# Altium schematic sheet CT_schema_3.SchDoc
size 451 x 443 mm
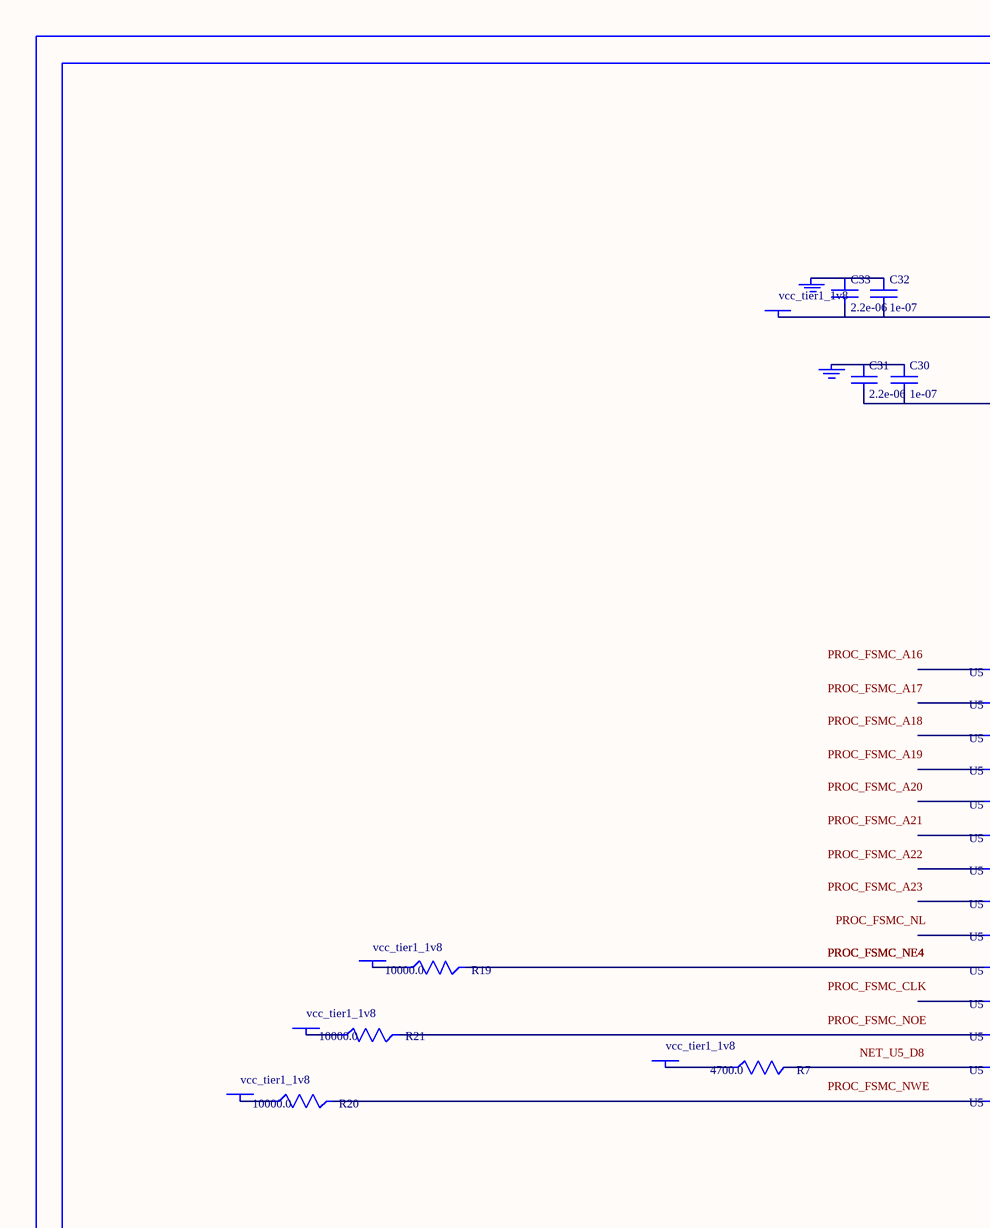
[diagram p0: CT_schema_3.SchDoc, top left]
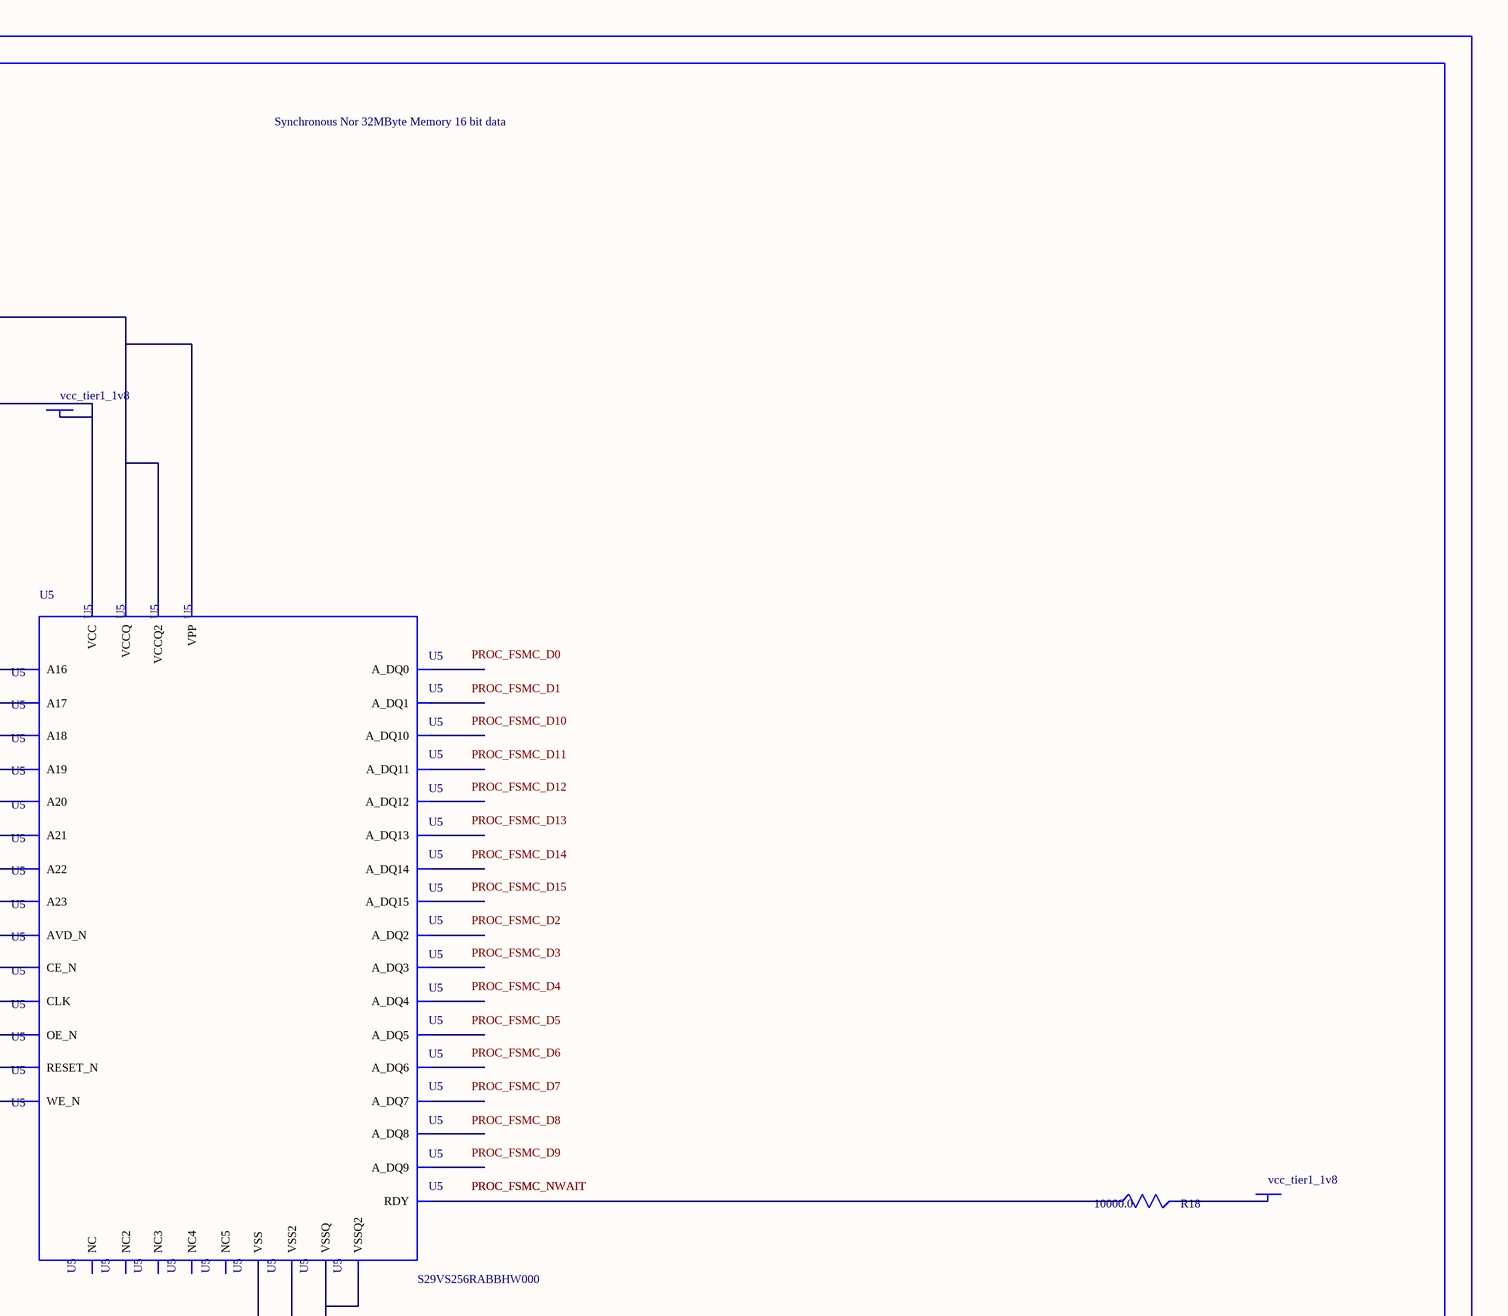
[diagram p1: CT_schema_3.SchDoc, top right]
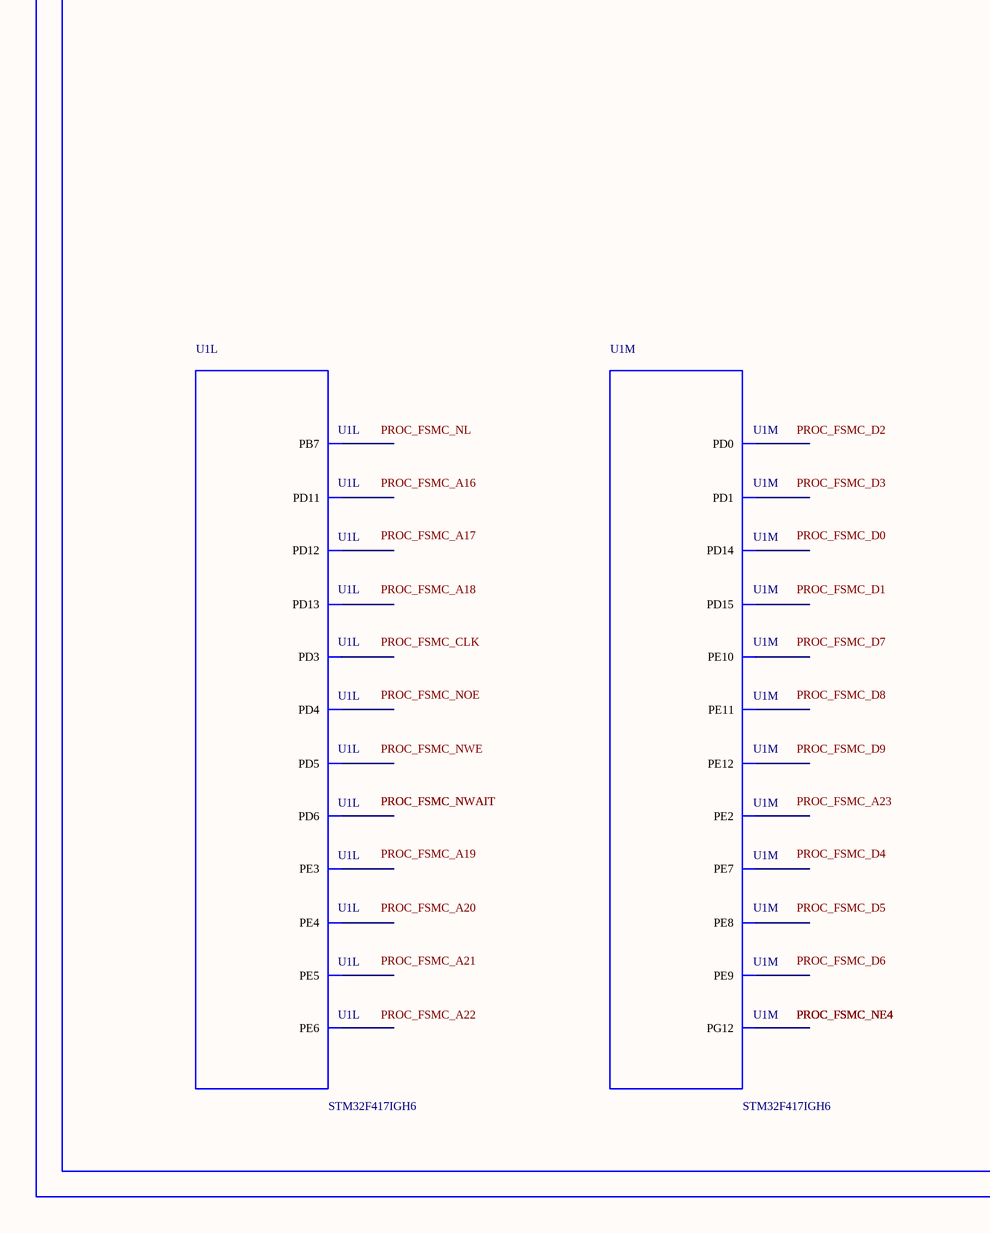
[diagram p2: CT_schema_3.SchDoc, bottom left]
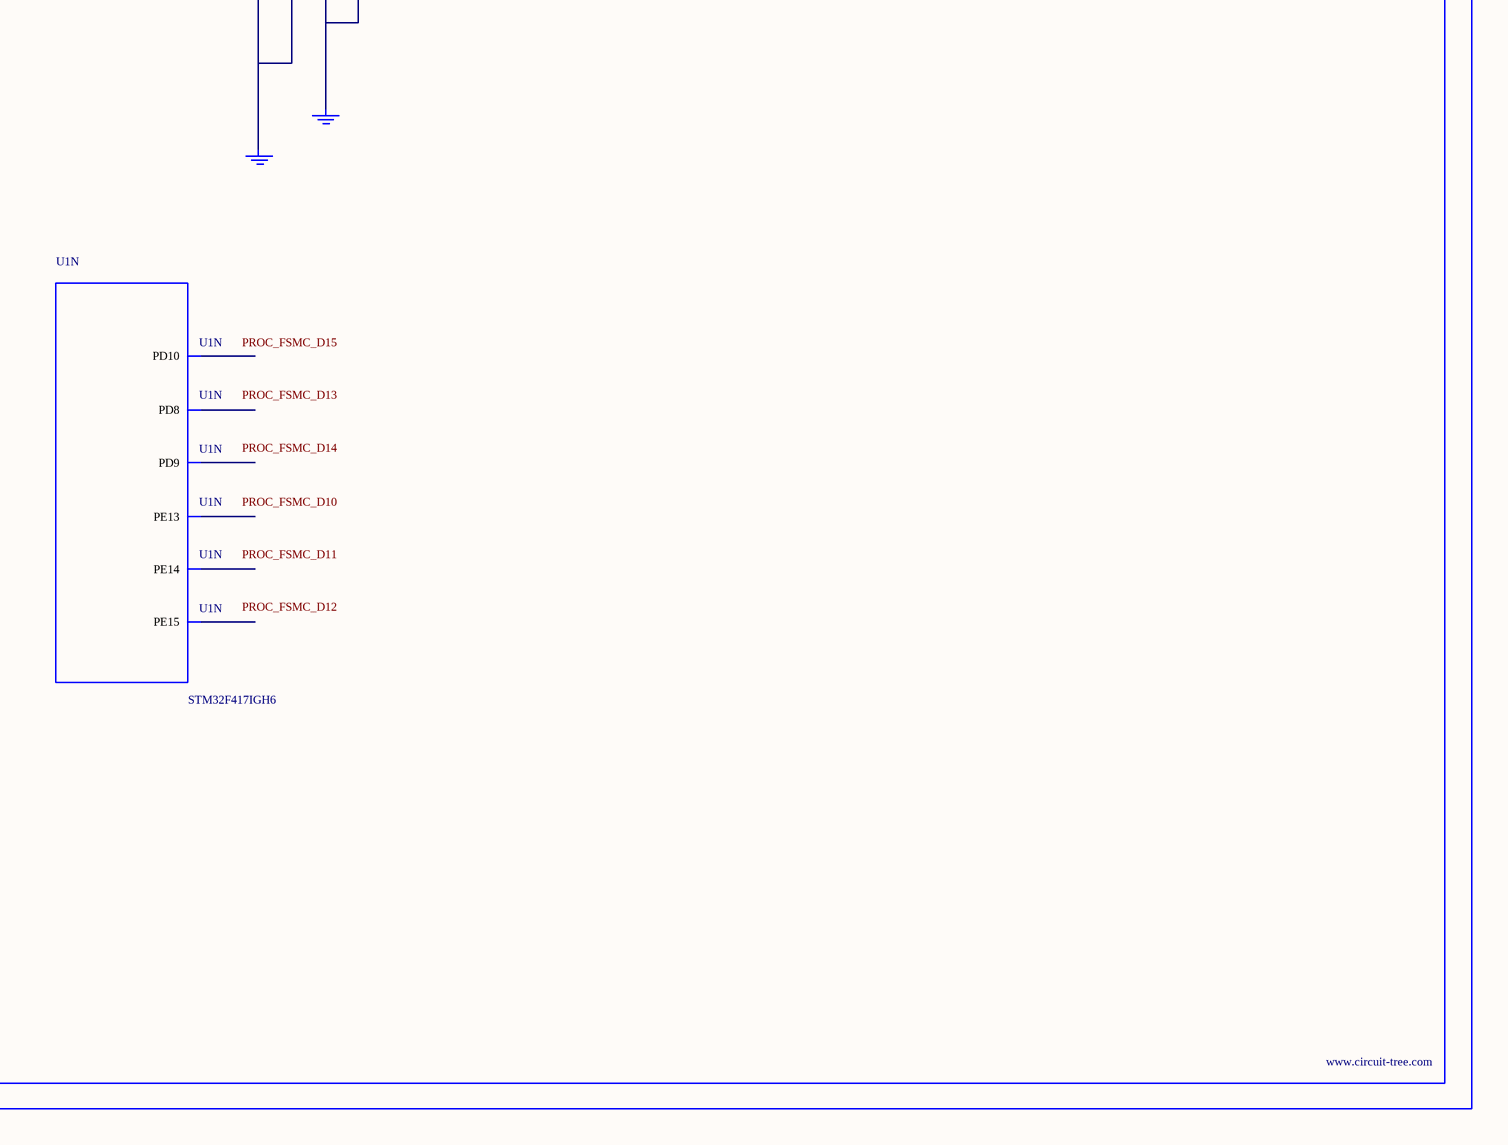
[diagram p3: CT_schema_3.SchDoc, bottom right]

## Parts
BORDER2  (no value)
C30  1e-07  [C0402]
C31  2.2e-06  [C0603]
C32  1e-07  [C0402]
C33  2.2e-06  [C0603]
GND_INSTANCE_2_0  (no value)
GND_INSTANCE_2_1  (no value)
GND_INSTANCE_2_2  (no value)
GND_INSTANCE_2_3  (no value)
POWER_INSTANCE_2_0  vcc_tier1_1v8
POWER_INSTANCE_2_1  vcc_tier1_1v8
POWER_INSTANCE_2_2  vcc_tier1_1v8
POWER_INSTANCE_2_3  vcc_tier1_1v8
POWER_INSTANCE_2_4  vcc_tier1_1v8
POWER_INSTANCE_2_5  vcc_tier1_1v8
POWER_INSTANCE_2_6  vcc_tier1_1v8
R7  4700.0  [R0603]
R18  10000.0  [R0603]
R19  10000.0  [R0603]
R20  10000.0  [R0603]
R21  10000.0  [R0603]
U1  STM32F417IGH6  [UFBGA176_25]  (parts L,M,N of 15)
U5  S29VS256RABBHW000  [S29VS256RABBHW000]

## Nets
NetC30_1: C30.1 C31.1 GND_INSTANCE_2_0.0(GND)
NetC30_2: C30.2 C31.2 POWER_INSTANCE_2_0.0(PWR) U5.C7(VCC)
NetC32_1: C32.1 C33.1 GND_INSTANCE_2_1.0(GND)
NetC32_2: C32.2 C33.2 POWER_INSTANCE_2_1.0(PWR) U5.C9(VPP) U5.D3(VCCQ) U5.F10(VCCQ2)
NetGND_INSTANCE_2_2_0: GND_INSTANCE_2_2.0(GND) U5.C5(VSS) U5.D12(VSS2)
NetGND_INSTANCE_2_3_0: GND_INSTANCE_2_3.0(GND) U5.E3(VSSQ) U5.F5(VSSQ2)
NetPOWER_INSTANCE_2_2_0: POWER_INSTANCE_2_2.0(PWR) R18.2
NetPOWER_INSTANCE_2_3_0: POWER_INSTANCE_2_3.0(PWR) R19.1
NetPOWER_INSTANCE_2_4_0: POWER_INSTANCE_2_4.0(PWR) R20.1
NetPOWER_INSTANCE_2_5_0: POWER_INSTANCE_2_5.0(PWR) R21.1
NetPOWER_INSTANCE_2_6_0: POWER_INSTANCE_2_6.0(PWR) R7.1
NetR7_2: R7.2 U5.D8(RESET_N)
NetR18_1: R18.1 U5.C3(RDY)
NetR19_2: R19.2 U5.D11(CE_N)
NetR20_2: R20.2 U5.C8(WE_N)
NetR21_2: R21.2 U5.E12(OE_N)

Not connected (* = marked no-connect by the designer): U1 A1(PE3) A2(PE2) B1(PE4) B2(PE5) B3(PE6) B5(PB7) B8(PG12) B11(PD6) B12(PD0) C11(PD5) C12(PD1) D10(PD4) D11(PD3) L14(PD15) M14(PD14) M15(PD13) N11(PE13) N13(PD12) N14(PD11) N15(PD10) P8(PE8) P9(PE9) P10(PE11) P11(PE14) P14(PD9) P15(PD8) R8(PE7) R9(PE10) R10(PE12) R11(PE15); U5 A1(NC) A14(NC2) C4(A21) C6(CLK) C10(A19) C11(A17) C12(A22) D4(A16) D5(A20) D6(AVD_N) D7(A23) D9(NC3) D10(A18) E4(A_DQ8) E5(A_DQ9) E6(A_DQ2) E7(A_DQ3) E8(A_DQ12) E9(A_DQ13) E10(A_DQ6) E11(A_DQ7) F3(A_DQ0) F4(A_DQ1) F6(A_DQ10) F7(A_DQ11) F8(A_DQ4) F9(A_DQ5) F11(A_DQ14) F12(A_DQ15) H1(NC4) H14(NC5)

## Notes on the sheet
- Labels drawn without touching a wire or pin: NET_U5_D8, PROC_FSMC_A16, PROC_FSMC_A17, PROC_FSMC_A18, PROC_FSMC_A19, PROC_FSMC_A20, PROC_FSMC_A21, PROC_FSMC_A22, PROC_FSMC_A23, PROC_FSMC_CLK, PROC_FSMC_D0, PROC_FSMC_D1, PROC_FSMC_D2, PROC_FSMC_D3, PROC_FSMC_D4, PROC_FSMC_D5, PROC_FSMC_D6, PROC_FSMC_D7, PROC_FSMC_D8, PROC_FSMC_D9, PROC_FSMC_D10, PROC_FSMC_D11, PROC_FSMC_D12, PROC_FSMC_D13, PROC_FSMC_D14, PROC_FSMC_D15, PROC_FSMC_NL, PROC_FSMC_NOE, PROC_FSMC_NWE

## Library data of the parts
BORDER2 = BORDER_PAGE2
C30 C32 = C0402C104K3RACTU
C31 C33 = C0603C225K8RACTU
GND_INSTANCE_2_0-GND_INSTANCE_2_3 = GND
POWER_INSTANCE_2_0-POWER_INSTANCE_2_6 = PWR
R7 = RC0603JR-074K7L
R18-R21 = RC0603JR-0710KL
